// Mitsubishi GX Works2 project: 模拟停车场进出场程序   PLC: FX3U/FX3UC

PROGRAM MAIN
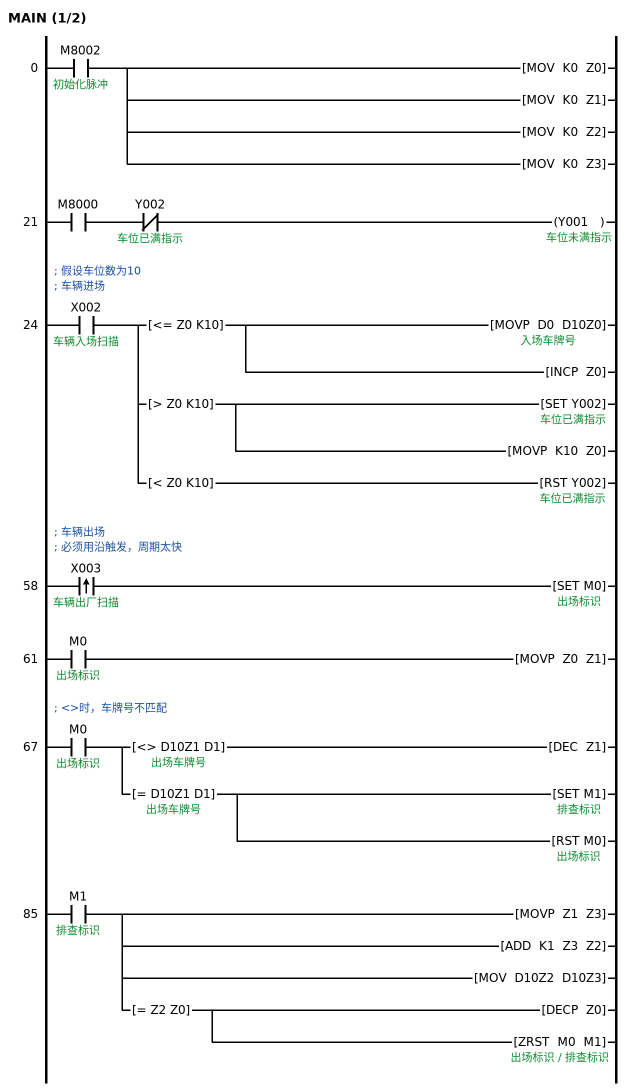
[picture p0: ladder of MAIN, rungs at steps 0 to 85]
0     LD      M8002  ; 初始化脉冲
      MOV     K0 Z0
      MOV     K0 Z1
      MOV     K0 Z2
      MOV     K0 Z3
21    LD      M8000
      ANI     Y002  ; 车位已满指示
      OUT     Y001  ; 车位未满指示
; 假设车位数为10
; 车辆进场
24    LD      X002  ; 车辆入场扫描
      MPS
      AND<=   Z0 K10
      MOVP    D0 D10Z0  ; 入场车牌号
        [note] 车牌号存入库
      INCP    Z0
        [note] 占用车位+1
      MRD
      AND>    Z0 K10
      SET     Y002  ; 车位已满指示
      MOVP    K10 Z0
      MPP
      AND<    Z0 K10
      RST     Y002  ; 车位已满指示
; 车辆出场
; 必须用沿触发，周期太快
58    LDP     X003  ; 车辆出厂扫描
      SET     M0  ; 出场标识
61    LD      M0  ; 出场标识
      MOVP    Z0 Z1
        [note] 把总占用数代入Z1
; <>时，车牌号不匹配
67    LD      M0  ; 出场标识
      MPS
      AND<>   D10Z1 D1  ; 出场车牌号
      DEC     Z1
        [note] Z1排除1个，继续排查
      MPP
      AND=    D10Z1 D1  ; 出场车牌号
      SET     M1  ; 排查标识
      RST     M0  ; 出场标识
        [note] 复位M0，确保M0、M1不互相影响
85    LD      M1  ; 排查标识
      MOVP    Z1 Z3
        [note] Z1代入Z3，确保Z1不被改变
      ADD     K1 Z3 Z2
      MOV     D10Z2 D10Z3
        [note] 出场车牌后的往前移一位
      AND=    Z2 Z0
      DECP    Z0
        [note] 排查完占用车位数-1
      ZRST    M0 M1
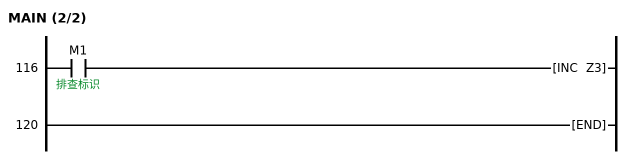
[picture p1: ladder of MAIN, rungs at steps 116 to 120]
116   LD      M1  ; 排查标识
      INC     Z3
        [note] 逐个上移
120   END
END_PROGRAM

// device comments not shown above
D10  ; 车牌号存储库
